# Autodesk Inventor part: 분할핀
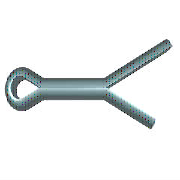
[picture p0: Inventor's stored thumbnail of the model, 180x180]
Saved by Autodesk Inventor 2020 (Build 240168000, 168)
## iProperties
IsCustomPart: 1
Created: 2012-02
Part Number: 분할핀
Material: 강철
Description: 분할 핀
Document SubType Name: Modeling
Standard: ISO 1234
Designer: mdu-01
Standard Revision: Second edition 1997-11-01
Standards Organization: ISO
Language: ko-KR
Size Designation: 2 x 14
Categories: <MemberInstance><Categories><Category DisplayName="조임쇠" InternalName="e4da775c-781d-43d5-af7c-5136215cf5a6" Mnemonic="FSTN"><Category DisplayName="핀" InternalNa
Density: 7.85 g/cm^3
Appearance: 파란색 - 벽 페인트 - 광택
Author: mdu-01
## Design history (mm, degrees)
sketch "스케치1"
  geometry: L1 (0, 0.9)-(8, 0.9); L2 (0, -0.9)-(8, -0.9); L3 (8, 0.9)-(14, 3.199); L4 (14, 3.199)-(14.301, 2.414); L5 (14.301, 2.414)-(8, 0); L6 (8, 0)-(16.801, -3.372); L7 (16.801, -3.372)-(16.5, -4.157); L8 (16.5, -4.157)-(8, -0.9); L9 (0, 0)-(-1.832, -0.821); L10 (0, 0)-(-1.832, 0.821); L11 (0, 0.9)-(0, -0.9); L12 (0, 0.9)-(-1.384, 1.604); L13 (0, -0.9)-(-1.384, -1.604); L14 (-4, 0)-(8, 0); L15 (8, 0.9)-(8, -0.9); A1 r 1.8 centre (-2.2, 0) between (-1.384, 1.604) and (-1.384, -1.604); A2 r 0.9 centre (-2.2, 0) between (-1.832, 0.821) and (-1.832, -0.821); 1 further point
  constraints: 30 end point, 5 point on circle, 4 parallel, 4 perpendicular, 4 point on line, 4 tangent, 2 centre point, 2 midpoint, 1 coincident, 1 horizontal
  dimensions: "d0" = 8 distance of L1.start L1.end (= MSIAB); "d1" = 14 horizontal distance of L1.start L3.end (= SNLG); "d2" = 159.037 deg angle of L1 L3; "d3" = 159.037 deg angle of L2 L8; "d4" = 2.5 horizontal distance of L3.end L7.end (= LGDIF); "d5" = 0.9 radius of A2 (= -0.5 x SNND1 + 0.5 x KBR); "d6" = 1.8 radius of A1 (= 0.5 x KBR); "d7" = 0.9 distance from line of L1 L9.start (= 0.5 x SNND1); "d8" = 0.9 distance between parallel lines of L2 L14 (= 0.5 x SNND1); "d9" = 2.2 distance from line of L11 A1.centre (= KOL - 0.5 x KBR)
extrude "본체" new body sketch "스케치1" stored distance "d10" = 1.8 (= SNND1); taper "d11" = 0 deg
workaxis "Work Axis1"
workplane "Work Plane1"
body "Solid1"
fillet "모깎기" dims "d12" = 0.72 (= 0.4 x SNND1)
node "작업 평면2"
other parameters: "SNND" = 2 [user parameter], "SNLG" = 14 [user parameter; used in 1 equation term], "SNND1" = 1.8 [user parameter; used in 5 equation terms], "KBR" = 3.6 [user parameter; used in 3 equation terms], "KOL" = 4 [user parameter; used in 1 equation term], "LGDIF" = 2.5 [user parameter; used in 1 equation term], "MSIAB" = 8 [user parameter; used in 1 equation term], "d15" = 0, "d16" = 0, "d17" = 0, "NNDMAX" = 9 [user parameter], "DSH" = 4 [user parameter], "NNDMIN" = 7 [user parameter]
